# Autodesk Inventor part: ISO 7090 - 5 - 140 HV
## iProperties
Created: 2001-09
Part Number: ISO 7090 - 5 - 140 HV
Catalog Web Link: file:///D:/Program%20Files/Autodesk/Inventor%205/Content/Iso/index.htm?doNavigateId=2A71B2AD-F337-496A-BFDA-377136DC7EA2|E4DE417A115D465B864BC6220D089EA|true
Description: Washer
Document SubType Name: Standard Catalog Part
Standard: ISO 7090 - 5 - 140 HV
Designer: Martin Budgell
Control State: 0
Master: False
Checked Out: False
Shininess: 64.0
Angle Display Precision: 2
Document Length Units: 11269
Document Angle Units: 11279
Document Time Units: 11290
Document Mass Units: 11283
Document Length Units Precision: 3
Document Angle Units Precision: 2
Compacted: True
CLASSIFICATION: 31161807 un/spsc
MANUFACTURER: ISO Standard System
Density: 0.0
Volumn: 0.0
Area: 0.0
PropertySet Name: Model Information
Author: Martin Budgell
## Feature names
1. Base1
